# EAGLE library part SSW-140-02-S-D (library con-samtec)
THROUGH-HOLE .025" SQ POST SOCKET Source: Samtec SSW.pdf
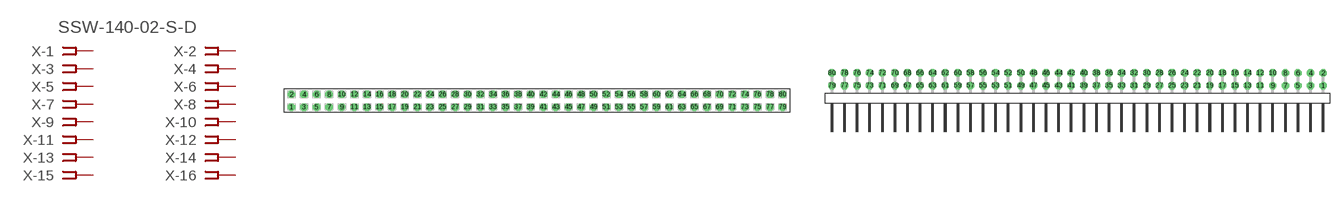
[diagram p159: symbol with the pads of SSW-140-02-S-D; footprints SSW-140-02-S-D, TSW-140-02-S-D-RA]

Designator prefix X; gates -1=FPINV -2=FPIN -3=FPIN -4=FPIN -5=FPIN -6=FPIN -7=FPIN -8=FPIN -9=FPIN -10=FPIN -11=FPIN -12=FPIN -13=FPIN -14=FPIN -15=FPIN -16=FPIN -17=FPIN -18=FPIN -19=FPIN -20=FPIN -21=FPIN -22=FPIN -23=FPIN -24=FPIN -25=FPIN -26=FPIN -27=FPIN -28=FPIN -29=FPIN -30=FPIN -31=FPIN -32=FPIN -33=FPIN -34=FPIN -35=FPIN -36=FPIN -37=FPIN -38=FPIN -39=FPIN -40=FPIN -41=FPIN -42=FPIN -43=FPIN -44=FPIN -45=FPIN -46=FPIN -47=FPIN -48=FPIN -49=FPIN -50=FPIN -51=FPIN -52=FPIN -53=FPIN -54=FPIN -55=FPIN -56=FPIN -57=FPIN -58=FPIN -59=FPIN -60=FPIN -61=FPIN -62=FPIN -63=FPIN -64=FPIN -65=FPIN -66=FPIN -67=FPIN -68=FPIN -69=FPIN -70=FPIN -71=FPIN -72=FPIN -73=FPIN -74=FPIN -75=FPIN -76=FPIN -77=FPIN -78=FPIN -79=FPIN -80=FPIN

## SSW-140-02-S-D (MPN: SSW-140-02-S-D; OC_FARNELL: unknown; OC_NEWARK: 11P9955)  [SSW-140-02-S-D]
1  -1:1  pas
2  -2:1  pas
3  -3:1  pas
4  -4:1  pas
5  -5:1  pas
6  -6:1  pas
7  -7:1  pas
8  -8:1  pas
9  -9:1  pas
10  -10:1  pas
11  -11:1  pas
12  -12:1  pas
13  -13:1  pas
14  -14:1  pas
15  -15:1  pas
16  -16:1  pas
17  -17:1  pas
18  -18:1  pas
19  -19:1  pas
20  -20:1  pas
21  -21:1  pas
22  -22:1  pas
23  -23:1  pas
24  -24:1  pas
25  -25:1  pas
26  -26:1  pas
27  -27:1  pas
28  -28:1  pas
29  -29:1  pas
30  -30:1  pas
31  -31:1  pas
32  -32:1  pas
33  -33:1  pas
34  -34:1  pas
35  -35:1  pas
36  -36:1  pas
37  -37:1  pas
38  -38:1  pas
39  -39:1  pas
40  -40:1  pas
41  -41:1  pas
42  -42:1  pas
43  -43:1  pas
44  -44:1  pas
45  -45:1  pas
46  -46:1  pas
47  -47:1  pas
48  -48:1  pas
49  -49:1  pas
50  -50:1  pas
51  -51:1  pas
52  -52:1  pas
53  -53:1  pas
54  -54:1  pas
55  -55:1  pas
56  -56:1  pas
57  -57:1  pas
58  -58:1  pas
59  -59:1  pas
60  -60:1  pas
61  -61:1  pas
62  -62:1  pas
63  -63:1  pas
64  -64:1  pas
65  -65:1  pas
66  -66:1  pas
67  -67:1  pas
68  -68:1  pas
69  -69:1  pas
70  -70:1  pas
71  -71:1  pas
72  -72:1  pas
73  -73:1  pas
74  -74:1  pas
75  -75:1  pas
76  -76:1  pas
77  -77:1  pas
78  -78:1  pas
79  -79:1  pas
80  -80:1  pas

## SSW-140-02-S-D-RA (MPN: SSW-140-02-S-D-RA; OC_FARNELL: unknown; OC_NEWARK: 11P9956)  [TSW-140-02-S-D-RA]
Pads as for SSW-140-02-S-D

## Footprint SSW-140-02-S-D (pad centres in mm)
THROUGH-HOLE .025" SQ POST SOCKET Source: Samtec SSW.pdf
drill 1 pad 1.5 octagon: 1 -49.53,-1.27; 2 -49.53,1.27; 3 -46.99,-1.27; 4 -46.99,1.27; 5 -44.45,-1.27; 6 -44.45,1.27; 7 -41.91,-1.27; 8 -41.91,1.27; 9 -39.37,-1.27; 10 -39.37,1.27; 11 -36.83,-1.27; 12 -36.83,1.27; 13 -34.29,-1.27; 14 -34.29,1.27; 15 -31.75,-1.27; 16 -31.75,1.27; 17 -29.21,-1.27; 18 -29.21,1.27; 19 -26.67,-1.27; 20 -26.67,1.27; 21 -24.13,-1.27; 22 -24.13,1.27; 23 -21.59,-1.27; 24 -21.59,1.27; 25 -19.05,-1.27; 26 -19.05,1.27; 27 -16.51,-1.27; 28 -16.51,1.27; 29 -13.97,-1.27; 30 -13.97,1.27; 31 -11.43,-1.27; 32 -11.43,1.27; 33 -8.89,-1.27; 34 -8.89,1.27; 35 -6.35,-1.27; 36 -6.35,1.27; 37 -3.81,-1.27; 38 -3.81,1.27; 39 -1.27,-1.27; 40 -1.27,1.27; 41 1.27,-1.27; 42 1.27,1.27; 43 3.81,-1.27; 44 3.81,1.27; 45 6.35,-1.27; 46 6.35,1.27; 47 8.89,-1.27; 48 8.89,1.27; 49 11.43,-1.27; 50 11.43,1.27; 51 13.97,-1.27; 52 13.97,1.27; 53 16.51,-1.27; 54 16.51,1.27; 55 19.05,-1.27; 56 19.05,1.27; 57 21.59,-1.27; 58 21.59,1.27; 59 24.13,-1.27; 60 24.13,1.27; 61 26.67,-1.27; 62 26.67,1.27; 63 29.21,-1.27; 64 29.21,1.27; 65 31.75,-1.27; 66 31.75,1.27; 67 34.29,-1.27; 68 34.29,1.27; 69 36.83,-1.27; 70 36.83,1.27; 71 39.37,-1.27; 72 39.37,1.27; 73 41.91,-1.27; 74 41.91,1.27; 75 44.45,-1.27; 76 44.45,1.27; 77 46.99,-1.27; 78 46.99,1.27; 79 49.53,-1.27; 80 49.53,1.27

## Footprint TSW-140-02-S-D-RA (pad centres in mm)
THROUGH-HOLE .025" SQ POST HEADER Source: Samtec TSW.pdf
drill 1 pad 1.5 octagon: 1 49.53,1.524; 2 49.53,4.064; 3 46.99,1.524; 4 46.99,4.064; 5 44.45,1.524; 6 44.45,4.064; 7 41.91,1.524; 8 41.91,4.064; 9 39.37,1.524; 10 39.37,4.064; 11 36.83,1.524; 12 36.83,4.064; 13 34.29,1.524; 14 34.29,4.064; 15 31.75,1.524; 16 31.75,4.064; 17 29.21,1.524; 18 29.21,4.064; 19 26.67,1.524; 20 26.67,4.064; 21 24.13,1.524; 22 24.13,4.064; 23 21.59,1.524; 24 21.59,4.064; 25 19.05,1.524; 26 19.05,4.064; 27 16.51,1.524; 28 16.51,4.064; 29 13.97,1.524; 30 13.97,4.064; 31 11.43,1.524; 32 11.43,4.064; 33 8.89,1.524; 34 8.89,4.064; 35 6.35,1.524; 36 6.35,4.064; 37 3.81,1.524; 38 3.81,4.064; 39 1.27,1.524; 40 1.27,4.064; 41 -1.27,1.524; 42 -1.27,4.064; 43 -3.81,1.524; 44 -3.81,4.064; 45 -6.35,1.524; 46 -6.35,4.064; 47 -8.89,1.524; 48 -8.89,4.064; 49 -11.43,1.524; 50 -11.43,4.064; 51 -13.97,1.524; 52 -13.97,4.064; 53 -16.51,1.524; 54 -16.51,4.064; 55 -19.05,1.524; 56 -19.05,4.064; 57 -21.59,1.524; 58 -21.59,4.064; 59 -24.13,1.524; 60 -24.13,4.064; 61 -26.67,1.524; 62 -26.67,4.064; 63 -29.21,1.524; 64 -29.21,4.064; 65 -31.75,1.524; 66 -31.75,4.064; 67 -34.29,1.524; 68 -34.29,4.064; 69 -36.83,1.524; 70 -36.83,4.064; 71 -39.37,1.524; 72 -39.37,4.064; 73 -41.91,1.524; 74 -41.91,4.064; 75 -44.45,1.524; 76 -44.45,4.064; 77 -46.99,1.524; 78 -46.99,4.064; 79 -49.53,1.524; 80 -49.53,4.064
